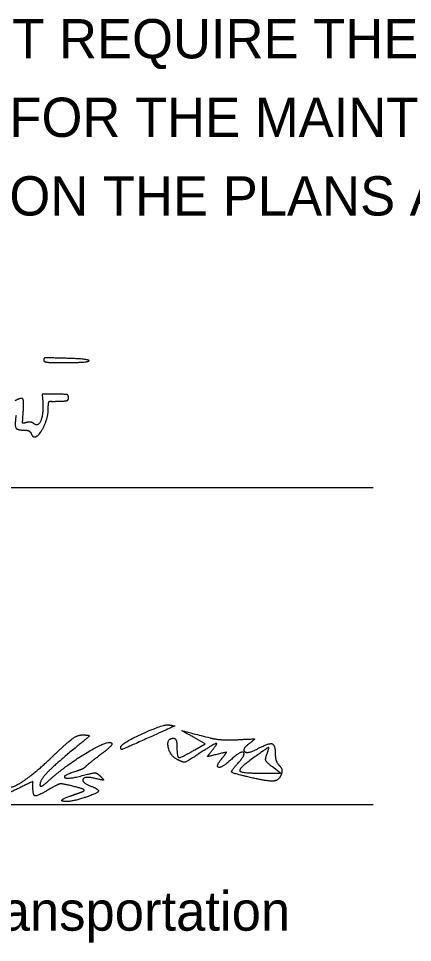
# Model space of a CAD drawing. Extents: x 0 to 34, y 0 to 22.
# Drawn here: x 26.766 to 28.168, y 7.305 to 10.597 of the extents above; entities that cross this region are included whole.
import ezdxf

# ---------------------------------------------------------------- set-up
doc = ezdxf.new("R2010")
doc.units = 0
doc.layers.add('GM_X_Minor_Lake', color=7, linetype='Continuous')
doc.layers.add('GM_X_Minor_Lake_Text', color=7, linetype='Continuous')

msp = doc.modelspace()

# ---------------------------------------------------------------- linework, layer by layer
at = {"layer": 'GM_X_Minor_Lake'}
for p, q in [((27.1295, 8.001), (27.1295, 8.001)), ((27.582, 7.8948), (27.582, 7.8948))]:
    msp.add_line(p, q, dxfattribs=at)
for points in [[(26.8966, 9.2583), (26.8497, 9.2583), (26.8519, 9.2282)], [(27.3933, 7.9914), (27.4297, 8.0129), (27.3889, 8.0359)], [(27.642, 7.9079), (27.6982, 7.908), (27.6695, 7.9301)]]:
    msp.add_lwpolyline(points, dxfattribs=at)
for points in [[(26.9304, 9.3864), (26.8636, 9.3882), (26.8555, 9.3873), (26.8555, 9.3783)], [(26.9335, 9.3708), (27.0179, 9.3714), (27.0154, 9.3841), (26.9304, 9.3864)], [(26.8555, 9.3783), (26.8555, 9.3735), (26.8865, 9.3705), (26.9335, 9.3708)], [(26.9435, 9.2463), (26.9435, 9.2556), (26.9329, 9.2583), (26.8966, 9.2583)], [(26.7823, 9.1906), (26.7857, 9.2343), (26.7766, 9.2478), (26.7525, 9.2349)], [(26.8519, 9.2282), (26.8547, 9.1882), (26.8354, 9.1411), (26.8211, 9.153)], [(26.8715, 9.205), (26.8715, 9.2211), (26.8742, 9.2339), (26.8775, 9.2334)], [(26.8775, 9.2334), (26.8808, 9.2328), (26.897, 9.2328), (26.9135, 9.2334)], [(26.9135, 9.2334), (26.9344, 9.234), (26.9435, 9.2379), (26.9435, 9.2463)], [(26.795, 9.1575), (26.7808, 9.1538), (26.7796, 9.157), (26.7823, 9.1906)], [(26.8229, 9.1063), (26.8376, 9.1063), (26.8715, 9.1751), (26.8715, 9.205)], [(26.7571, 9.1828), (26.7513, 9.1467), (26.7608, 9.1303), (26.7876, 9.1303)], [(26.8211, 9.153), (26.8153, 9.1578), (26.8036, 9.1598), (26.795, 9.1575)], [(26.7876, 9.1303), (26.7976, 9.1303), (26.8078, 9.1249), (26.8104, 9.1183)], [(26.8104, 9.1183), (26.8129, 9.1117), (26.8185, 9.1063), (26.8229, 9.1063)], [(27.1295, 8.001), (27.1295, 8.0134), (27.2823, 8.0837), (27.3012, 8.08)], [(27.3012, 8.08), (27.3219, 8.076), (27.3226, 8.0764), (27.201, 8.0218)], [(26.8951, 7.9753), (26.9403, 8.019), (26.9774, 8.0447), (26.9951, 8.0444)], [(26.9951, 8.0444), (27.0194, 8.0439), (27.0156, 8.0375), (26.967, 7.9975)], [(27.3889, 8.0359), (27.3461, 8.06), (27.3452, 8.06), (27.4482, 8.0336)], [(26.8763, 7.8841), (26.93, 7.9329), (27.0769, 8.0229), (27.0938, 8.0172)], [(27.0938, 8.0172), (27.1022, 8.0144), (27.087, 7.9957), (27.0599, 7.9755)], [(27.201, 8.0218), (27.1385, 7.9937), (27.1295, 7.9911), (27.1295, 8.001)], [(27.3305, 7.9569), (27.304, 7.9711), (27.293, 8.0324), (27.317, 8.0324)], [(27.317, 8.0324), (27.3238, 8.0324), (27.3295, 8.0184), (27.3295, 8.0012)], [(27.3295, 8.0012), (27.3295, 7.9644), (27.3438, 7.9622), (27.3933, 7.9914)], [(27.4529, 7.9866), (27.4773, 8.0162), (27.4615, 8.0124), (27.4052, 7.9752)], [(27.4482, 8.0336), (27.4688, 8.0284), (27.5138, 8.0256), (27.5482, 8.0275)], [(27.5482, 8.0275), (27.6031, 8.0306), (27.608, 8.029), (27.5881, 8.0142)], [(27.5881, 8.0142), (27.5593, 7.9927), (27.5822, 7.9763), (27.6159, 7.9944)], [(27.6159, 7.9944), (27.6561, 8.0159), (27.6795, 8.0101), (27.6795, 7.9787)], [(26.7295, 7.8684), (26.7295, 7.8456), (26.8248, 7.907), (26.8951, 7.9753)], [(26.967, 7.9975), (26.8929, 7.9366), (26.842, 7.883), (26.842, 7.8663)], [(27.0599, 7.9755), (27.0328, 7.9553), (27.0079, 7.9353), (27.0045, 7.9311)], [(27.4052, 7.9752), (27.3652, 7.9487), (27.3519, 7.9454), (27.3305, 7.9569)], [(27.4723, 7.9749), (27.4392, 7.9667), (27.4374, 7.9678), (27.4529, 7.9866)], [(27.4924, 7.9642), (27.507, 7.9818), (27.5047, 7.983), (27.4723, 7.9749)], [(27.5462, 7.9428), (27.5767, 7.9764), (27.5551, 7.9874), (27.5211, 7.9554)], [(27.6497, 7.9756), (27.6596, 8.0014), (27.6514, 7.9983), (27.5888, 7.9527)], [(27.6695, 7.9301), (27.6491, 7.9458), (27.6434, 7.959), (27.6497, 7.9756)], [(27.6795, 7.9787), (27.6795, 7.9629), (27.6858, 7.9436), (27.6936, 7.9358)], [(27.5211, 7.9554), (27.4892, 7.9255), (27.4661, 7.9325), (27.4924, 7.9642)], [(27.582, 7.8948), (27.5272, 7.9077), (27.5215, 7.9154), (27.5462, 7.9428)], [(27.5888, 7.9527), (27.5461, 7.9217), (27.5626, 7.9078), (27.642, 7.9079)], [(27.6936, 7.9358), (27.7014, 7.928), (27.7044, 7.9128), (27.7003, 7.902)], [(26.9701, 7.9145), (26.9206, 7.8991), (26.9401, 7.8854), (26.9919, 7.8992)], [(27.0045, 7.9311), (27.001, 7.9268), (26.9856, 7.9194), (26.9701, 7.9145)], [(26.9919, 7.8992), (27.0302, 7.9095), (27.0455, 7.9089), (27.0575, 7.8966)], [(26.817, 7.8559), (26.817, 7.8788), (26.8159, 7.8788), (26.7698, 7.8559)], [(26.842, 7.8663), (26.842, 7.8588), (26.8574, 7.8668), (26.8763, 7.8841)], [(26.9621, 7.8609), (26.9233, 7.8708), (26.9065, 7.8691), (26.8789, 7.8528)], [(27.0388, 7.8892), (27.0021, 7.8982), (26.9889, 7.8751), (27.0232, 7.862)], [(27.0575, 7.8966), (27.0702, 7.8837), (27.0666, 7.8823), (27.0388, 7.8892)], [(27.7003, 7.902), (27.6922, 7.8809), (27.651, 7.8784), (27.582, 7.8948)], [(26.7698, 7.8559), (26.7324, 7.8374), (26.7138, 7.8351), (26.6807, 7.8446)], [(26.8789, 7.8528), (26.8339, 7.8262), (26.817, 7.8271), (26.817, 7.8559)], [(26.9482, 7.8259), (26.962, 7.8308), (26.9817, 7.8379), (26.992, 7.8417)], [(26.992, 7.8417), (27.0034, 7.8458), (26.9917, 7.8533), (26.9621, 7.8609)], [(27.0232, 7.862), (27.0538, 7.8502), (27.0449, 7.8353), (26.9981, 7.8199)], [(26.9981, 7.8199), (26.9515, 7.8045), (26.9042, 7.8102), (26.9482, 7.8259)]]:
    msp.add_open_spline(points, degree=2, dxfattribs=at)
at = {"layer": 'GM_X_Minor_Lake_Text'}
for p, q in [((24.5279, 8.9262), (28.0279, 8.9262)), ((24.5279, 7.7968), (28.0279, 7.7968))]:
    msp.add_line(p, q, dxfattribs=at)

# ---------------------------------------------------------------- texts
at = {"layer": 'GM_X_Minor_Lake'}
msp.add_text('Director, Department of Transportation', height=0.14, dxfattribs=at).set_placement((24.5279, 7.3468))
at = {"layer": 'GM_X_Minor_Lake_Text'}
for s, p in [('IMPROVEMENT WILL NOT REQUIRE THE CLOSING TO TRAFFIC OF THE HIGHWAY', (24.5279, 10.455)), ('AND THAT PROVISIONS FOR THE MAINTENANCE AND SAFETY OF TRAFFIC', (24.5279, 10.175)), ('WILL BE AS SET FORTH ON THE PLANS AND ESTIMATES.', (24.5279, 9.895))]:
    msp.add_text(s, height=0.14, dxfattribs=at).set_placement(p)

doc.saveas('drawing.dxf')
